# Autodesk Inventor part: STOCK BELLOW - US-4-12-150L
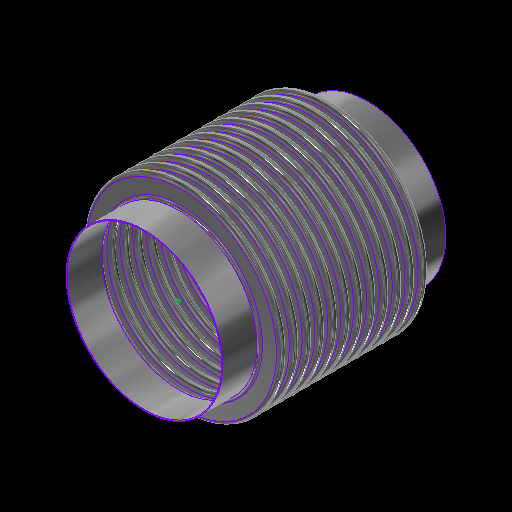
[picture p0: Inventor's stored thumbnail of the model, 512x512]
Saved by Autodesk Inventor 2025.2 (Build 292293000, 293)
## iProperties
Category: 22 GA (0.030 THICK)
RuleStatus: InUse
Created: 2024-01
Part Number: STOCK BELLOW - US-4-12-150L
Project: =STOCK BELLOWS: <Stock Number><SFILL>
Material: ASTM A240-304
Description: =STOCK BELLOWS: <Stock Number>, <SID_> I.D., <SOD_> O.D., <SPLY_> PLY, <Category>, <SNET_CONS> CONS.<PITCH_><STANGENT_> TANGENT<SFILL>
Document SubType Name: Sheet Metal
Designer: GS
Stock Number: U.S-4-12-150L
Surface Area: 3884.08 cm^2
Volume: 147.354 cm^3
Sheet Metal Rule: Default
Appearance: STAINLESS STEEL
Mass: 1187.27 g
Density: 8.05729 g/cm^3
THK: 0.036
ID: 3.500
OD: 4.250
CONS_: 2
PITCH: 0.500
TANGENT: 0.500
BELLOWS_UPSET: 0.000
d79: 1.000
d82: 1.000
d83: 26.000
d84: 24.000
d174: 8
d214: 8
STHK_: 0.030
SID_: 4.500
SOD_: 5.750
SPITCH_: 0.375
STANGENT__: 1.000
SBELLOWS_UPSET_: 0.000
SDIFF_TAN: 1.000
d252: 2
d275: 2
d287: 0.050
d289: 0.500
d290: 0.000
SOD_NECK: 4 9/16
PLY: 1
PSET: 4.178
PBAR: 1.035
COUNTER: 1.500
NET_TUBE: 3.071
CONS: 2
S_CONS: 0
NET_CONS: 2
ID_M: 88.90 mm
OD_M: 107.95 mm
THK_M: 0.91 mm
ID_U: 3.500 in
OD_U: 4.250 in
THK_U: 0.036 in
TANGENT2: 0.500
TAN_TO_TAN: 1.000 in
d80: 2.571
d81: 10
SID: 2.375
SCONS_: 12
SPITCH: 0.250
STANGENT_: 1.000
SBELLOWS_UPSET: 0.000
SNET_CONS: 12
SS_CONS: 0
SCONS: 8
d190: 8
d191: 1
d192: 1
d193: 8
d194: 0
SIZE: 4.00
PRESSURE: 150
d230: 8
STANGENT: 4.000
SPLY_: 1
d233: 8
d234: 0
d263: 2
d265: 1
d268: 2
d269: 0
d286: 2
d288: 1
d291: 2
d292: 0
SREROLL: 0.750
BLETP: 1.000 ul
PRES_Copy: 85
MATTABLE: 20 GA (0.036 THICK)
PART_NUMBER: U.S-4-12-150L
PITCH_: =, <SPITCH_> PITCH,
CFILL: .
SFILL: .
MESH: ,
COMP: 1.05
EXT: 0.53
LAT: 0.30
ANG: 573
ASR: 816
LSR: 1429
ANSR: 42
PRES: 150
COMPM: 10.5
EXTM: 5.25
LATM: 3.00
ASRM: 142.906
PRESM: 10.342
LSRM: 250.261
ANSRM: 7.355
TEMPMIN: 20
TEMPMAX: 800
TEMPMINM: -7
TEMPMAXM: 427
WEIGHTM: 1.187
WEIGHT: 2.617
Author: GS
Keywords: 20 GA (0.036 THICK)
Comments: =STOCK BELLOW - <STOCK NUMBER>
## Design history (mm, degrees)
sketch "Sketch2"
  geometry: L1 (0, -177.245)-(0, 562.856) reference; L2 (45.364, 0)-(44.45, 0); L3 (48.082, -2.718)-(50.343, -2.718); L4 (48.082, -3.632)-(50.343, -3.632); L5 (50.343, -9.982)-(48.082, -9.982); L6 (50.343, -9.068)-(48.082, -9.068); L7 (45.364, -12.7)-(44.45, -12.7); L8 (48.082, 0)-(48.082, -12.7); L9 (50.343, -6.35)-(53.975, -6.35); L10 (44.45, 0)-(44.45, -12.7); L11 (20.376, 102.841)-(20.376, 101.926); L12 (58.262, 457.127)-(58.262, 349.177); L13 (58.262, 444.427)-(58.262, 336.477); L14 (93.133, -58.817)-(93.133, -71.517); L15 (118.746, -66.401)-(118.746, -66.401); L16 (50.343, -9.068)-(50.343, -9.982); L17 (48.082, -9.068)-(48.082, -9.982); L18 (48.082, -9.525)-(50.343, -9.525); L19 (53.975, 0)-(53.975, -12.7); L20 (-50.343, -9.068)-(-50.343, -9.982); L21 (-50.343, -2.718)-(-48.082, -2.718); L22 (-50.343, -3.632)-(-48.082, -3.632); L23 (-48.082, -9.068)-(-50.343, -9.068); L24 (-50.343, -9.525)-(-48.082, -9.525); L25 (-48.082, -9.982)-(-50.343, -9.982); L26 (-48.082, -9.068)-(-48.082, -9.982); L27 (-44.45, 0.653)-(-44.45, -12.047); L28 (-48.082, -6.35)-(-44.45, -6.35); L29 (-50.343, 0.653)-(-50.343, -12.7); L30 (-53.061, 0)-(-53.975, 0); L31 (-53.975, 0)-(-53.975, -12.7); L32 (-53.061, -12.7)-(-53.975, -12.7); A1 r 2.718 centre (48.082, 0) between (45.364, 0) and (48.082, -2.718); A2 r 3.632 centre (48.082, 0) between (44.45, 0) and (48.082, -3.632); A3 r 3.632 centre (50.343, -6.35) between (50.343, -9.982) and (50.343, -2.718); A4 r 2.718 centre (50.343, -6.35) between (50.343, -9.068) and (50.343, -3.632); A5 r 2.718 centre (48.082, -12.7) between (48.082, -9.982) and (45.364, -12.7); A6 r 3.632 centre (48.082, -12.7) between (48.082, -9.068) and (44.45, -12.7); A7 r 3.175 centre (50.343, -6.35) between (50.343, -9.525) and (53.518, -6.35); A8 r 3.175 centre (48.082, -12.7) between (48.082, -9.525) and (44.907, -12.7); A9 r 2.718 centre (-50.343, -12.7) between (-50.343, -9.982) and (-53.061, -12.7); A10 r 2.718 centre (-48.082, -6.35) between (-48.082, -9.068) and (-48.082, -3.632); A11 r 3.175 centre (-48.082, -6.35) between (-48.082, -9.525) and (-44.907, -6.35); A12 r 3.632 centre (-48.082, -6.35) between (-48.082, -9.982) and (-48.082, -2.718); A13 r 3.175 centre (-50.343, -12.7) between (-50.343, -9.525) and (-53.518, -12.7); A14 r 3.632 centre (-50.343, -12.7) between (-50.343, -9.068) and (-53.975, -12.7); A15 r 2.718 centre (-50.343, 0) between (-53.061, 0) and (-50.343, -2.718); A16 r 3.632 centre (-50.343, 0) between (-53.975, 0) and (-50.343, -3.632); 10 further points
  constraints: 62 end point, 38 point on circle, 20 tangent, 16 centre point, 12 parallel, 9 midpoint, 7 vertical, 6 coincident, 6 concentric, 6 point on line, 4 equal radius, 4 perpendicular, 3 horizontal, 1 collinear, 1 horizontal alignment, 10 other
  dimensions: "THK" = 0.9144 distance of L11.start L11.end; "ID" = 88.9 distance of L11.end point (20.376, 13.026); "OD" = 107.95 distance of L12.start L12.end; "PITCH" = 12.7 distance of L12.start L13.start; "TANGENT" = 12.7 distance of L14.start L14.end; "BELLOWS_UPSET" = 0 distance of L15.start L15.end; "d43" = 88.9 diameter of L10 L1 (= ID); "d44" = 107.95 diameter of L9.end L1 (= OD); "d45" = 0.9144 distance between parallel lines of L5 L6 (computed from THK, PLY); "d46" = 3.6322 radius of A3 (computed from PITCH, THK, PLY); "UPSET_PITCH" = 12.7 distance of L2.end L7.end (derived); "SIDEWALL_ANGLE" = 360 deg dimension on L3 L9 (derived); "CON_GAP" = 5.4356 distance of point (48.082, -9.068) point (48.082, -3.632) (derived); "TAN1" = 4.98728 dimension on A8 (derived); "TAN2" = 4.98728 dimension on A7 (derived); "LEG1" = 2.2606 distance of L18.start L18.end (derived); "d278" = 0.9144 distance between parallel lines of L25 L23 (derived); "d279" = 3.6322 radius of A12 (derived); "d280" = 12.7 distance of L30.end L31.end (derived); "d281" = 360 deg dimension on L21 L28 (derived); "d282" = 5.4356 distance of point (-50.343, -9.068) point (-50.343, -3.632) (derived); "d283" = 4.98728 dimension on A13 (derived); "d284" = 4.98728 dimension on A11 (derived); "d285" = 2.2606 distance of L24.start L24.end (derived); "d293" = 88.9 diameter of L27 L1 (derived); "d294" = 107.95 diameter of L31 L1 (derived)
  node "Sketch Rectangular Pattern1" dims "d31" = 25.4, "ID" = 88.9
  node "Sketch Rectangular Pattern2" dims "d39" = 25.4, "PITCH" = 12.7
revolve "CONS" stored, may be unused: angle "d48" = 90 deg
node "BELLOW MIDPLANE"
pattern_linear "Rectangular Pattern2" dims "d52" = 12.7 (= UPSET_PITCH)
sketch "Sketch5"
  geometry: C1 r 45.364 at (0, 0) reference; C2 r 44.45 at (0, 0) reference
extrude "TANGENT" new body sketch "Sketch5" distance "d53" = 12.7 (= TANGENT); taper "d54" = 0 deg
revolve "SAMETAN" stored, may be unused: angle "d65" = 90 deg
revolve "DIFFTAN" stored, may be unused: angle "d70" = 90 deg
sketch "Sketch9"
  geometry: L1 (53.319, 0)-(-53.319, 0) reference; L2 (0, -17.78)-(0, 17.78) reference; L3 (38.085, 0)-(-38.085, 0); L4 (38.085, -11.906)-(38.085, 11.906); L5 (25.385, -11.906)-(25.385, 11.906); L6 (13.15, 11.906)-(13.15, -11.906); L7 (-25.385, -11.906)-(-25.385, 11.906); L8 (-38.085, -11.906)-(-38.085, 11.906); L9 (37.291, -11.906)-(37.291, 11.906); L10 (38.085, -11.906)-(37.291, -11.906); L11 (38.085, 11.906)-(37.291, 11.906); L12 (13.546, 11.906)-(12.753, 11.906); L13 (12.753, 11.906)-(12.753, -11.906); L14 (12.753, -11.906)-(13.546, -11.906); L15 (13.546, -11.906)-(13.546, 11.906); L16 (-13.546, 11.906)-(-13.546, -11.906); L17 (-13.15, 11.906)-(-13.15, -11.906); L18 (-13.546, -11.906)-(-12.753, -11.906); L19 (-12.753, -11.906)-(-12.753, 11.906); L20 (-12.753, 11.906)-(-13.546, 11.906); L21 (-38.085, -11.906)-(-37.291, -11.906); L22 (-37.291, -11.906)-(-37.291, 11.906); L23 (-37.291, 11.906)-(-38.085, 11.906); L24 (-38.085, 11.906)-(-38.085, -11.906); L25 (38.085, -0.397)-(-38.085, -0.397); L26 (-38.085, -0.397)-(-38.085, 0.397); L27 (-38.085, 0.397)-(38.085, 0.397); L28 (38.085, 0.397)-(38.085, -0.397); L29 (-38.085, 11.906)-(38.085, 11.906); L30 (38.085, 11.906)-(38.085, 12.7); L31 (38.085, 12.7)-(-38.085, 12.7); L32 (-38.085, 12.7)-(-38.085, 11.906); L33 (38.085, -11.906)-(-38.085, -11.906); L34 (-38.085, -11.906)-(-38.085, -12.7); L35 (-38.085, -12.7)-(38.085, -12.7); L36 (38.085, -12.7)-(38.085, -11.906); 30 further points
  constraints: 68 end point, 13 midpoint, 13 parallel, 8 horizontal, 7 perpendicular, 6 equal length, 3 point on line, 2 vertical, 14 other
  dimensions: "d115" = 23.8125 distance of L4.start L4.end (derived); "d116" = 12.7 distance between parallel lines of L4 L5 (derived); "d117" = 12.23516 distance between parallel lines of L5 L6 (derived); "d125" = 38.53427 distance between parallel lines of L7 L6 (derived); "d127" = 12.7 distance between parallel lines of L8 L7 (derived); "d128" = 24.93516 distance between parallel lines of L6 L4 (derived); "d130" = 76.16943 distance between parallel lines of L8 L4 (derived); "RULER_THK" = 0.79375 distance between parallel lines of L4 L9; "d135" = 0.79375 distance of L13.end L14.end (derived); "d138" = 26.29911 distance of L13.end L16.end (derived); "d143" = 0.79375 distance of L22.end L8.end (derived); "d144" = 0.79375 distance between parallel lines of L27 L25 (derived)
extrude "RULER" join sketch "Sketch9" distance "d149" = 0.79375 (derived); taper "d150" = 0 deg
extrude "BARS" join sketch "Sketch9" distance "d151" = 0.79375 (derived); taper "d152" = 0 deg
pattern_linear "Rectangular Pattern4" dims "d155" = 26.29911 (derived)
sketch "Sketch13"
  geometry: L1 (93.149, -52.467)-(93.149, -77.867); L2 (57.912, 0)-(57.15, 0); L3 (57.912, -9.525)-(57.15, -9.525); L4 (70.263, -7.525)-(59.912, -7.525); L5 (70.263, -6.763)-(59.912, -6.763); L6 (70.263, -4.763)-(73.025, -4.763); L7 (59.912, -2)-(70.263, -2); L8 (59.912, 0)-(59.912, -9.525); L9 (57.15, 0)-(57.15, -9.525); L10 (58.254, -350.381)-(58.254, -496.431); L11 (58.254, -359.906)-(58.254, -505.956); L12 (58.254, -378.956)-(58.254, -525.006); L13 (58.254, -388.481)-(58.254, -534.531); L14 (58.254, -398.006)-(58.254, -544.056); L15 (58.254, -407.531)-(58.254, -553.581); L16 (58.254, -417.056)-(58.254, -563.106); L17 (58.254, -369.431)-(58.254, -515.481); L18 (20.376, 102.688)-(20.376, 101.926); L19 (59.912, -2.762)-(70.263, -2.762); L20 (0, -696.265)-(0, 235.847) reference; L21 (-23.752, 0)-(142.514, 0) reference; A1 r 2 centre (59.912, 0) between (57.912, 0) and (59.912, -2); A2 r 2 centre (59.912, -9.525) between (59.912, -7.525) and (57.912, -9.525); A3 r 2.762 centre (59.912, -9.525) between (59.912, -6.763) and (57.15, -9.525); A4 r 2 centre (70.263, -4.763) between (70.263, -6.763) and (70.263, -2.762); A5 r 2.762 centre (70.263, -4.763) between (70.263, -7.525) and (70.263, -2); A6 r 2.762 centre (59.912, 0) between (57.15, 0) and (59.912, -2.762); 6 further points; 1 other entity
  constraints: 38 end point, 15 point on circle, 9 tangent, 6 centre point, 6 parallel, 5 vertical alignment, 4 point on line, 4 vertical, 3 coincident, 3 concentric, 2 collinear, 2 equal radius, 1 horizontal, 1 perpendicular, 23 other
  dimensions: "SBELLOWS_UPSET_" = 0 distance of point (118.762, -66.401) point (118.762, -66.401); "STOTAL_THK_BELLOW__" = 0.762 distance between parallel lines of L4 L5 (derived); "d224" = 2.76225 radius of A5 (derived); "d225" = 9.525 distance of L2.end L3.end (derived); "SSIDEWALL_ANGLE_" = 360 deg dimension on L7 L6 (derived); "SSCON_GAP_" = 4.0005 distance of point (59.912, -6.763) point (59.912, -2.762) (derived); "d235" = 114.3 diameter of L9 L20 (derived); "d236" = 146.05 diameter of L6.end L20 (derived)
  node "Sketch Rectangular Pattern4" dims "d228" = 25.4
  node "Sketch Rectangular Pattern5" dims "d229" = 25.4
revolve "SBELLOW" stored, may be unused: angle "d197" = 90 deg
pattern_linear "Rectangular Pattern5" dims "d204" = 9.525 (derived)
revolve "STANGENT" stored, may be unused: angle "d240" = 90 deg
revolve "SSAMETAN" stored, may be unused: angle "d241" = 90 deg
revolve "SDIFFTAN" stored, may be unused: angle "d246" = 90 deg
revolve "INVCON" stored, may be unused: angle "d295" = 90 deg
pattern_linear "Rectangular Pattern6" dims "d298" = 12.7 (derived)
revolve "INVTANGENT" stored, may be unused: angle "d302" = 90 deg
revolve "INVSAMETAN" stored, may be unused: angle "d307" = 90 deg
revolve "INVDIFFTAN" stored, may be unused: angle "d312" = 90 deg
sketch "ID BELLOW MOUNT CALC"
  geometry: L1 (44.45, 0)-(38.1, 0); L2 (38.1, 0)-(38.1, 12.7); L3 (38.1, 12.7)-(44.45, 12.7); L4 (44.45, 12.7)-(44.45, 0); L5 (36.513, 12.7)-(35.598, 12.7); L6 (35.598, 12.7)-(35.598, 0); L7 (35.598, 0)-(36.513, 0); L8 (36.513, 0)-(36.513, 12.7); L9 (0, -2.54)-(0, 15.24) reference; L10 (-8.89, 0)-(53.34, 0) reference; 1 further point
  constraints: 16 end point, 5 parallel, 2 collinear, 2 horizontal, 2 perpendicular
  dimensions: "d314" = 12.7 distance of L5.end L6.end (derived); "d315" = 0.9144 distance of L5.start L5.end (derived); "IG" = 1.5875 distance between parallel lines of L2 L8; "PIPE_OD" = 88.9 diameter of L4 L9; "PIPE_WALL" = 6.35 distance of L2.end L3.end; "ID_MT_BELLOW" = 71.1962 diameter of L6 L9 (derived)
revolve "CFILL" stored, may be unused: angle "d320" = 90 deg
pattern_linear "Rectangular Pattern7" dims "d323" = 12.7 (derived)
revolve "SFILL" stored, may be unused: angle "d324" = 90 deg
pattern_linear "Rectangular Pattern8" dims "d327" = 9.525 (derived)
node "STOCK BELLOW MIDPLANE"
node "BELLOW"
sketch "Sketch6"
  geometry: L1 (-12.7, 45.364)-(0, 45.364); L2 (0, 45.364)-(0, 44.45); L3 (0, 44.45)-(-12.7, 44.45); L4 (-12.7, 44.45)-(-12.7, 45.364); L5 (10.16, 0)-(-60.96, 0) reference; L6 (-38.1, -89.422)-(-38.1, 153.44) reference; 1 further point
  constraints: 8 end point, 2 parallel, 1 horizontal, 1 perpendicular
  dimensions: "d61" = 12.7 distance of L2.end L3.end (derived); "d62" = 0.9144 distance of L1.end L2.end (derived); "d63" = 88.9 diameter of L3 L5 (derived); "d64" = 25.4 distance between parallel lines of L4 L6 (derived)
sketch "Sketch12"
  geometry: 1 further point
sketch "Sketch14"
  geometry: L1 (-25.4, 57.912)-(0, 57.912); L2 (0, 57.912)-(0, 57.15); L3 (0, 57.15)-(-25.4, 57.15); L4 (-25.4, 57.15)-(-25.4, 57.912); L5 (5.08, 0)-(-30.48, 0) reference; L6 (0, -11.582)-(0, 69.494) reference; 1 further point
  constraints: 8 end point, 2 parallel, 1 collinear, 1 horizontal, 1 perpendicular
  dimensions: "d237" = 0.762 distance of L3.end L1.start (derived); "d238" = 114.3 diameter of L3 L5 (derived); "d239" = 25.4 distance of L1.start L1.end (derived); "SOD_NECK" = 115.824 diameter of L1 L5 (derived)
sketch "Sketch15"
  geometry: L1 (-11.582, 0)-(69.494, 0) reference; L2 (57.15, -114.3)-(57.912, -114.3); L3 (57.912, -114.3)-(57.912, -139.7); L4 (57.912, -139.7)-(57.15, -139.7); L5 (57.15, -139.7)-(57.15, -114.3); L6 (0, -170.18)-(0, 43.18) reference; 1 further point
  constraints: 8 end point, 2 parallel, 1 horizontal, 1 perpendicular
  dimensions: "d205" = 25.4 distance of L4.end L2.start (derived); "d206" = 0.762 distance of L3.end L4.end (derived); "d207" = 114.3 diameter of L5 L6 (derived); "d208" = 114.3 distance between parallel lines of L1 L2 (derived)
node "TANGENT_"
node "SAME_TAN"
sketch "Sketch8"
  geometry: L1 (45.364, -25.4)-(44.45, -25.4); L2 (44.45, -25.4)-(44.45, -38.1); L3 (44.45, -38.1)-(45.364, -38.1); L4 (45.364, -38.1)-(45.364, -25.4); L5 (0, -48.26)-(0, 22.86) reference; L6 (-89.422, 0)-(153.44, 0) reference; 1 further point
  constraints: 8 end point, 2 parallel, 1 horizontal, 1 perpendicular
  dimensions: "d66" = 88.9 diameter of L2 L5 (derived); "TOTAL_THK_BELLOW" = 0.9144 distance of L2.end L3.end (derived); "d68" = 25.4 distance between parallel lines of L1 L6 (derived); "d69" = 12.7 distance of L1.end L2.end (derived)
node "DIFF_TAN"
node "Sketch Rectangular Pattern3" dims "d138" = 26.29911 (derived), "d141" = 25.4
node "SBELLOW_"
node "STANGENT_"
node "SSAME_TAN"
sketch "Sketch16"
  geometry: L1 (57.912, -114.3)-(57.15, -114.3); L2 (57.15, -114.3)-(57.15, -139.7); L3 (57.15, -139.7)-(57.912, -139.7); L4 (57.912, -139.7)-(57.912, -114.3); L5 (0, -170.18)-(0, 43.18) reference; L6 (-11.582, 0)-(69.494, 0) reference; 1 further point
  constraints: 8 end point, 2 parallel, 1 horizontal, 1 perpendicular
  dimensions: "SDIFF_TAN" = 25.4 distance of L3.end L1.start; "d243" = 0.762 distance of L2.end L3.end (derived); "d244" = 114.3 distance between parallel lines of L1 L6 (derived); "d245" = 114.3 diameter of L2 L5 (derived)
node "SDIFF_TAN"
body "Solid15"
sketch "Sketch17"
  geometry: L1 (53.975, 12.7)-(53.061, 12.7); L2 (53.061, 12.7)-(53.061, 0); L3 (53.061, 0)-(53.975, 0); L4 (53.975, 0)-(53.975, 12.7); L5 (0, -2.54)-(0, 15.24) reference; L6 (-10.795, 0)-(64.77, 0) reference; 2 further points
  constraints: 8 end point, 2 parallel, 1 horizontal, 1 midpoint, 1 perpendicular, 1 point on line
  dimensions: "INVTANGENT" = 12.7 distance of L3.end L1.start (derived); "d300" = 0.9144 distance of L1.start L1.end (derived); "d301" = 107.95 diameter of L4 L5 (derived)
body "Solid16"
sketch "Sketch18"
  geometry: L1 (53.975, -25.4)-(53.061, -25.4); L2 (53.061, -25.4)-(53.061, -38.1); L3 (53.061, -38.1)-(53.975, -38.1); L4 (53.975, -38.1)-(53.975, -25.4); L5 (-10.795, 0)-(64.77, 0) reference; L6 (0, -48.26)-(0, 22.86) reference; 1 further point
  constraints: 8 end point, 2 parallel, 1 horizontal, 1 perpendicular
  dimensions: "d303" = 25.4 distance between parallel lines of L1 L5 (derived); "d304" = 12.7 distance of L3.end L1.start (derived); "d305" = 0.9144 distance of L2.end L3.end (derived); "d306" = 107.95 diameter of L4 L6 (derived)
body "Solid17"
sketch "Sketch19"
  geometry: L1 (53.975, -25.4)-(53.061, -25.4); L2 (53.061, -25.4)-(53.061, -38.1); L3 (53.061, -38.1)-(53.975, -38.1); L4 (53.975, -38.1)-(53.975, -25.4); L5 (0, -48.26)-(0, 22.86) reference; L6 (-10.795, 0)-(64.77, 0) reference; 1 further point
  constraints: 8 end point, 2 parallel, 1 horizontal, 1 perpendicular
  dimensions: "d308" = 12.7 distance of L1.end L2.end (derived); "d309" = 107.95 diameter of L4 L5 (derived); "d310" = 0.9144 distance of L2.end L3.end (derived); "d311" = 25.4 distance between parallel lines of L1 L6 (derived)
body "Solid18"
body "Solid19"
body "Solid20"
other parameters: "BMPL" = -57.15, "PSET" = 106.1212 (computed from OD, THK, PLY) [user parameter], "PBAR" = 26.29911 (= 0.570796 x PITCH + OD - ID) [user parameter; used in 1 equation term], "COUNTER" = 15 [user parameter], "NET_TUBE" = 77.99823 (computed from CONS_, PBAR, TANGENT) [user parameter], "S_CONS" = 0 [user parameter; used in 1 equation term], "ID_M" = 88.9 (= ID) [user parameter], "OD_M" = 107.95 (= OD) [user parameter], "THK_M" = 0.9144 (= THK) [user parameter], "ID_U" = 88.9 (= ID) [user parameter], "OD_U" = 107.95 (= OD) [user parameter], "THK_U" = 0.9144 (= THK) [user parameter], "D_UNITS" = 0 [user parameter], "TANGENT2" = 12.7 [user parameter], "TAN_TO_TAN" = 25.4 [user parameter], "OD_NECK" = 90.7288 [user parameter], "d79" = 25.4, "d80" = 65.29823 [user parameter], "d82" = 25.4, "d83" = 660.4, "d84" = 609.6, "sa_0" = 4, "FRAME_THK" = 0.79375 [user parameter], "CON_FLAT" = 12.23516 [user parameter], "SID" = 60.325 [user parameter], "SPITCH" = 6.35 [user parameter], "STANGENT_" = 25.4 [user parameter], "SBELLOWS_UPSET" = 0 [user parameter], "SS_CONS" = 0 [user parameter], "STAN_TO_TAN_" = 114.3 [user parameter], "d100" = 0.762 [user parameter], "d191" = 25.4 [user parameter], "d194" = 0 [user parameter], "STANGENT" = 101.6 [user parameter], "d234" = 0 [user parameter], "SUPSET_PITCH_" = 9.525 [user parameter], "d269" = 0 [user parameter], "d287" = 1.27, "d289" = 12.7, "d290" = 0, "d292" = 0 [user parameter], "Thickness" = 3.048 (derived), "KFactor" = 4.4, "BendRadius" = 3.048 (derived), "BendReliefWidth" = 3.048 (derived), "BendReliefDepth" = 1.524 (derived), "CornerReliefSize" = 12.192 (derived), "SeamGap" = 0.00508, "MinimumRemnant" = 6.096 (derived), "TransitionRadius" = 3.048 (derived), "JacobiRadiusSize" = 3.048 (derived), "GapSize" = 3.048 (derived), "SREROLL" = 19.05 [user parameter], "CUR_STK_PITCH" = 9.525 [user parameter], "d328" = -57.15 (derived), "LSR" = 14290 [user parameter], "BLETP" = 1 [user parameter], "ASRM" = 1429.0608 [user parameter], "PRESM" = 103.41975 [user parameter], "LSRM" = 2502.6077 [user parameter], "ANSRM" = 73.5546 [user parameter], "TEMPMIN" = 2664.83333 [user parameter], "TEMPMAX" = 6998.16667 [user parameter], "TEMPMINM" = 2664.83333 [user parameter], "TEMPMAXM" = 6998.16667 [user parameter], "WEIGHT" = 11.87273 [user parameter], "WEIGHTM" = 0.01187 [user parameter]
